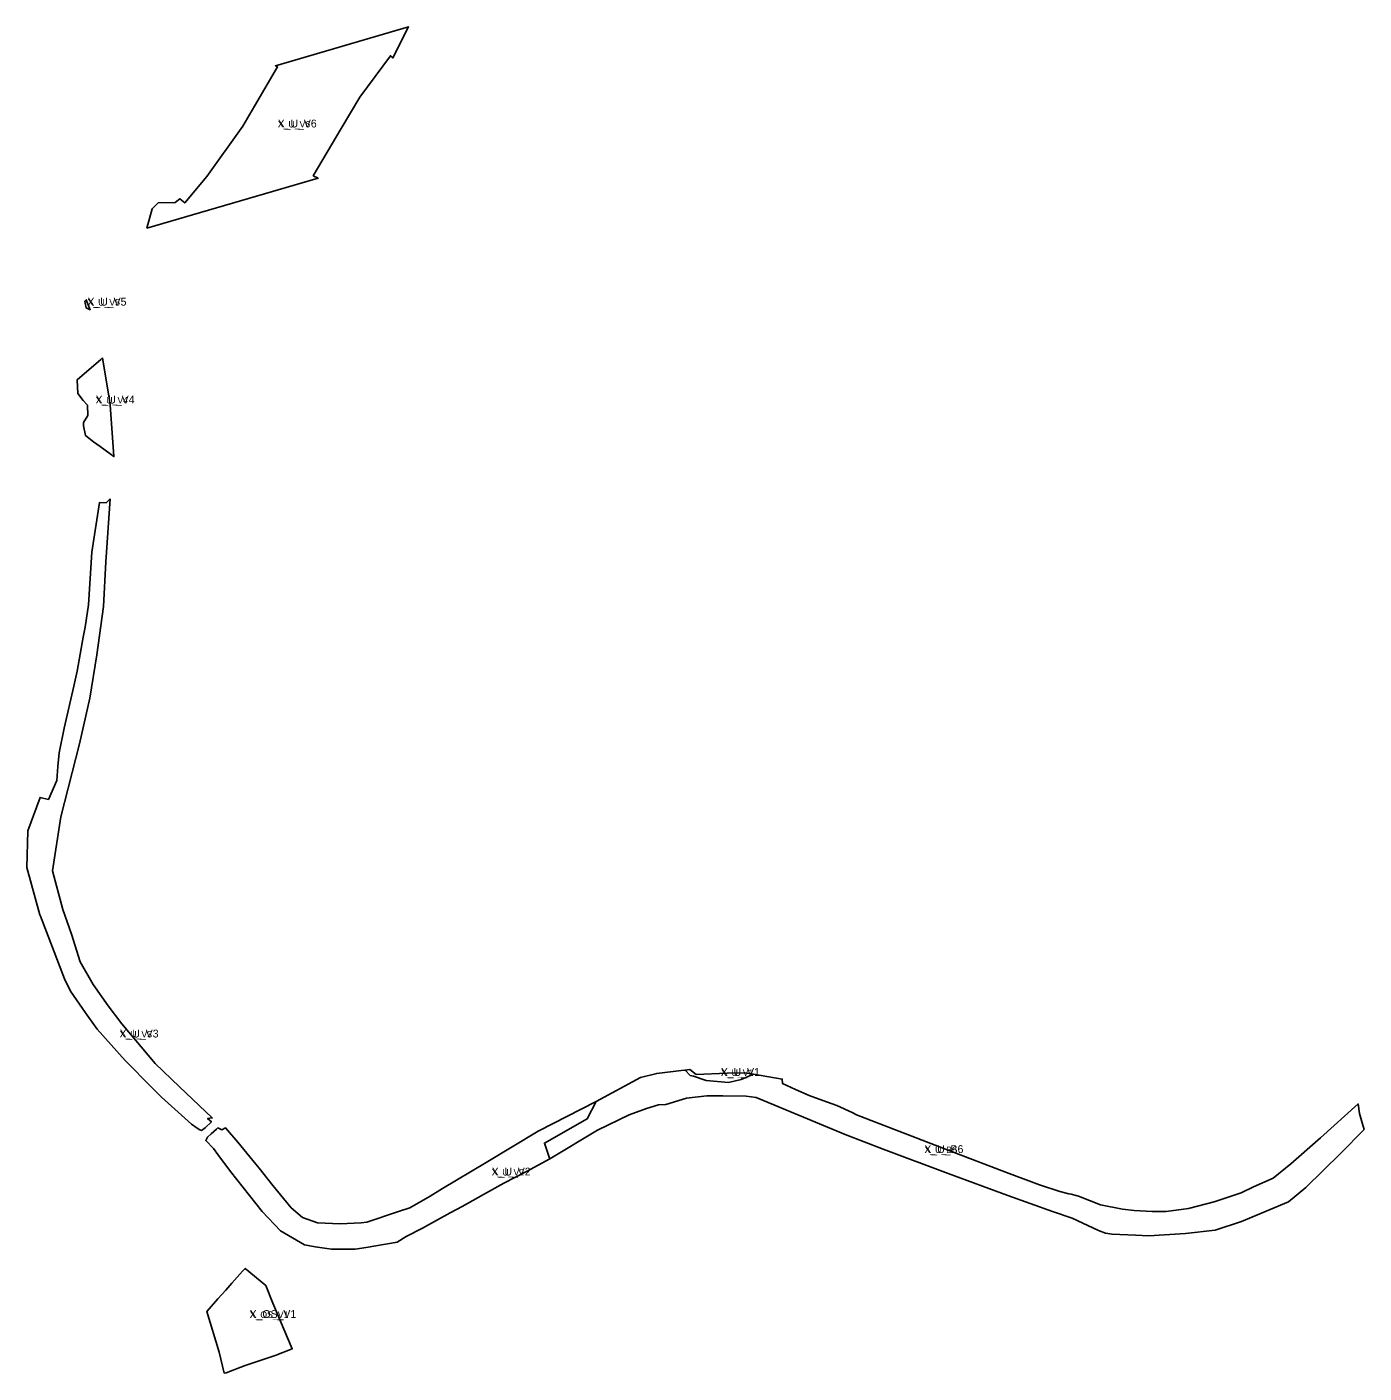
# Model space of a CAD drawing. Extents: x -532058 to -529750, y -1180391 to -1176703.
# Drawn here: x -532058 to -531033, y -1178431 to -1177399 of the extents above; entities that cross this region are included whole.
import ezdxf

# ---------------------------------------------------------------- set-up
doc = ezdxf.new("R2010")
doc.units = 0
doc.layers.add('96140023', color=7, linetype='Continuous')
doc.layers.add('ID_VPO', color=7, linetype='Continuous')

msp = doc.modelspace()

# ---------------------------------------------------------------- linework, layer by layer
at = {"layer": '96140023'}
for points in [[(-531883.3, -1177459.7), (-531865.6, -1177429.5), (-531867.3, -1177428.6), (-531765.2, -1177398.8), (-531777.2, -1177422.6), (-531779.1, -1177421), (-531802.6, -1177452.7), (-531816.9, -1177476.8), (-531838.3, -1177512.9), (-531834.5, -1177514.8), (-531965.7, -1177553), (-531961.7, -1177538.3), (-531957.1, -1177533.6), (-531944.1, -1177533.4), (-531940.6, -1177530.5), (-531936.8, -1177533.8), (-531919.7, -1177513.4), (-531892.2, -1177474.9)], [(-532013, -1177610.7), (-532013.4, -1177609.1), (-532012.2, -1177608), (-532009.3, -1177615.7), (-532012.3, -1177614.3)], [(-531999.9, -1177652.4), (-531997.8, -1177665.1), (-531995.3, -1177680), (-531993.8, -1177688.6), (-531991, -1177728.2), (-531994, -1177726.2), (-532001.7, -1177720.5), (-532006.6, -1177716.8), (-532012.7, -1177712.1), (-532014.4, -1177704.7), (-532014.4, -1177702), (-532011.1, -1177696.8), (-532011.4, -1177688.8), (-532014.7, -1177685.2), (-532018.8, -1177679.9), (-532019.2, -1177669.3), (-532001.1, -1177653.8)], [(-531993.9, -1177760.6), (-531997.3, -1177808.9), (-531998.9, -1177843.2), (-532004.1, -1177880.3), (-532009.6, -1177913.4), (-532017.5, -1177948.5), (-532031.7, -1178004.3), (-532038, -1178045.8), (-532030.2, -1178075.3), (-532023.6, -1178094.4), (-532016.8, -1178115.4), (-532007, -1178132.9), (-531995.5, -1178149.3), (-531985, -1178163), (-531959.4, -1178193.4), (-531940.7, -1178211.3), (-531915.7, -1178235.2), (-531919.2, -1178235.7), (-531916.3, -1178238.1), (-531921.1, -1178242.7), (-531923.8, -1178244.8), (-531925.3, -1178244.3), (-531927.2, -1178243), (-531931.6, -1178239.9), (-531954.6, -1178219.2), (-531961.7, -1178212.1), (-531982.4, -1178191.1), (-532003.9, -1178167.2), (-532012.9, -1178154.6), (-532024.2, -1178138.1), (-532028.8, -1178128.6), (-532047.4, -1178080.6), (-532047.7, -1178079.4), (-532057.7, -1178043.2), (-532057.1, -1178015.2), (-532047.6, -1177989.5), (-532041.3, -1177991), (-532034.8, -1177976.6), (-532034.1, -1177965.9), (-532033, -1177955.2), (-532029.2, -1177936.4), (-532021.7, -1177904.2), (-532019.3, -1177892.8), (-532014.5, -1177866.7), (-532013, -1177858.9), (-532010.6, -1177841.9), (-532008, -1177801.4), (-532002, -1177763.4), (-531997, -1177763.6)], [(-531657, -1178266.5), (-531657.3, -1178265.2), (-531661, -1178254.5), (-531628.2, -1178236), (-531621.5, -1178222.7), (-531587.4, -1178204.1), (-531574.9, -1178201.1), (-531556.2, -1178198.8), (-531553.2, -1178198.5), (-531549.3, -1178202.7), (-531546.9, -1178203.1), (-531537.2, -1178206.4), (-531519.9, -1178208), (-531510.2, -1178205.6), (-531500.8, -1178201.6), (-531478.7, -1178205.4), (-531478.5, -1178208.9), (-531468.5, -1178213.3), (-531458.1, -1178218.1), (-531447.6, -1178221.9), (-531436.9, -1178225.6), (-531425.2, -1178231), (-531421.9, -1178232.7), (-531347, -1178261.8), (-531306.9, -1178277), (-531281.5, -1178286.5), (-531266.1, -1178291.7), (-531259.1, -1178293.3), (-531257.3, -1178293.7), (-531251.8, -1178295.1), (-531234.9, -1178301.9), (-531217.9, -1178305), (-531208.9, -1178306.1), (-531195.3, -1178306.9), (-531184.5, -1178306.9), (-531167.4, -1178304.5), (-531147.8, -1178299.4), (-531127.1, -1178292.7), (-531117.5, -1178287.9), (-531102.4, -1178281.3), (-531088.9, -1178270.4), (-531066.3, -1178250.5), (-531037.2, -1178224.4), (-531036.3, -1178231.7), (-531034.2, -1178239), (-531032.8, -1178244), (-531050.9, -1178262.5), (-531077.4, -1178288.5), (-531090.8, -1178299.5), (-531126.7, -1178314.7), (-531147, -1178321.3), (-531169.6, -1178323.8), (-531197.8, -1178325.6), (-531207.9, -1178325), (-531226, -1178324.4), (-531230.9, -1178323.5), (-531236.3, -1178321.5), (-531256.6, -1178312.1), (-531271.5, -1178306.9), (-531305.9, -1178294.7), (-531351.7, -1178277.9), (-531401.4, -1178259), (-531430.5, -1178247.9), (-531498.8, -1178219.5), (-531506.5, -1178218.5), (-531524.3, -1178218.2), (-531536.5, -1178218.2), (-531552.1, -1178220), (-531567.9, -1178224.8), (-531573.5, -1178225.2), (-531582.7, -1178227.9), (-531596.1, -1178232.8), (-531620.3, -1178244.6)], [(-531519.9, -1178208), (-531537.2, -1178206.4), (-531546.9, -1178203.1), (-531549.3, -1178202.7), (-531553.2, -1178198.5), (-531549.7, -1178198.1), (-531544.7, -1178201.9), (-531520.9, -1178200.8), (-531507.5, -1178200.6), (-531500.8, -1178201.6), (-531510.2, -1178205.6)], [(-531674.7, -1178276.2), (-531692.1, -1178285.3), (-531707.7, -1178293.9), (-531724.2, -1178303.2), (-531733.2, -1178308), (-531743.1, -1178313.4), (-531754.5, -1178319.7), (-531767.1, -1178326.2), (-531773.8, -1178330.5), (-531790.2, -1178333.3), (-531797.7, -1178334.6), (-531806, -1178335.9), (-531824.3, -1178335.7), (-531836.7, -1178334), (-531845, -1178332.5), (-531863.4, -1178321.8), (-531877.5, -1178306.8), (-531901.7, -1178276.3), (-531911.3, -1178263.2), (-531914.6, -1178258.6), (-531920.7, -1178252.4), (-531919.4, -1178250), (-531916.6, -1178247.5), (-531912.4, -1178243.8), (-531911.3, -1178242.8), (-531908.3, -1178244.2), (-531905.4, -1178242.8), (-531904, -1178244.6), (-531896, -1178253.8), (-531882.3, -1178270.6), (-531879.6, -1178273.8), (-531869.3, -1178286.9), (-531855.1, -1178304.1), (-531846.4, -1178311.4), (-531834.9, -1178315.6), (-531817.7, -1178316.3), (-531801.4, -1178315.5), (-531797.1, -1178315), (-531772.8, -1178307), (-531764.1, -1178304), (-531748.6, -1178295.1), (-531739.2, -1178289.3), (-531705.6, -1178269.4), (-531665.8, -1178245.4), (-531621.5, -1178222.7), (-531628.2, -1178236), (-531661, -1178254.5), (-531657.3, -1178265.2), (-531657, -1178266.5)], [(-531906.5, -1178430.8), (-531910.3, -1178414.8), (-531919.7, -1178383.6), (-531911.3, -1178373.9), (-531905.3, -1178367.2), (-531900.6, -1178361.8), (-531892.6, -1178352.6), (-531890.4, -1178350.5), (-531874.7, -1178363.6), (-531869.2, -1178377.3), (-531854.3, -1178412.3), (-531867.5, -1178417.3), (-531890.5, -1178424.9), (-531905, -1178430.5)]]:
    msp.add_lwpolyline(points, close=True, dxfattribs=at)

# ---------------------------------------------------------------- texts
for s, rotation, p in [('X_U_V6', 360, (-531865.5, -1177475.9)), ('X_U_V5', 0, (-532011.3, -1177612.5)), ('X_U_V4', 0, (-532005.1, -1177687.5)), ('X_U_V3', 0, (-531986.7, -1178173.5)), ('X_U_V1', 360, (-531525.8, -1178203)), ('X_U_B6', 360, (-531369.8, -1178262.1)), ('X_U_V2', 360, (-531701.5, -1178279.3)), ('X_OS_V1', 0, (-531887, -1178388.5))]:
    msp.add_text(s, height=5, rotation=rotation, dxfattribs=at).set_placement(p)
at = {"layer": 'ID_VPO'}
for s, rotation, p in [('X_U_V6', 360, (-531865.5, -1177475.9)), ('X_U_V5', 0, (-532011.3, -1177612.5)), ('X_U_V4', 360, (-532005.1, -1177687.5)), ('X_U_V3', 0, (-531986.7, -1178173.5)), ('X_U_V1', 360, (-531525.8, -1178203)), ('X_U_B6', 360, (-531369.8, -1178262.1)), ('X_U_V2', 360, (-531701.5, -1178279.3))]:
    msp.add_text(s, height=6, rotation=rotation, dxfattribs=at).set_placement(p)
msp.add_text('X_OS_V1', height=6, dxfattribs=at).set_placement((-531887, -1178388.5))

doc.saveas('drawing.dxf')
